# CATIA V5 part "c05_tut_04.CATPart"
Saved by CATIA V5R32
Part number: Part1
Bounding box of the stored display mesh (mm): x -150 to 0, y -16 to 54, z 0 to 74.999
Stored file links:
  D:\PROJECTS\Project 2022\CATIA V5 6R 2022\Resources\Tutorial Files\c05_catia_v5_6r2022_tut\c05_tut_04.CATPart
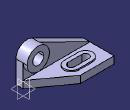
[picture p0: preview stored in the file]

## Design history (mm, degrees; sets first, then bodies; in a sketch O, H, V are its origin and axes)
Body1 (main body)
  Sketch1 on xy-plane, origin (0, 0, 0), H (1, 0, 0), V (0, 1, 0)
    line L1 (0, 0) -> (-150, 0)
    line L2 (-150, 0) -> (-150, 54)
    line L3 (-150, 54) -> (-75, 54)
    line L4 (-75, 54) -> (0, 0)
    length L2 = 54
    length L3 = 75
    length L1 = 150
    vertical: L2 V
    horizontal: L3 H, L1 H
  Pad1: profile Sketch1, direction (0, 0, 1), length 16
  Sketch2 on end face of Pad1, origin (0, 0, 16), H (1, 0, 0), V (0, 1, 0)
    construction line L1 (-114, 26) -> (-82, 26)
    point P1 (-114, 26)
    line L2 (-114, 42) -> (-82, 42)
    line L3 (-82, 10) -> (-114, 10)
    arc A1 centre (-82, 26) radius 16 from (-82, 42) to (-82, 10) cw
    arc A2 centre (-114, 26) radius 16 from (-114, 10) to (-114, 42) cw
    reference projected line E1 (-150, 0) -> (0, 0) from edge [face of Pad1 from Sketch1.L1 | end face of Pad1]
    reference projected line E2 (-150, 54) -> (-150, 0) from edge [face of Pad1 from Sketch1.L2 | end face of Pad1]
    distance L1 L2 = 16
    distance L3 E1 = 10
    length L2 = 32
    distance P1 E2 = 36
    horizontal: L1 H
    tangency: A1 L2, A2 L2, A1 L3, A2 L3
  Pad2: profile Sketch2, direction (0, 0, 1), length 3
  Sketch3 on face of Pad1 from Sketch1.L1, origin (0, 0, 0), H (1, 0, 0), V (0, 0, 1)
    line L1 (0, 0) -> (0, 50)
    arc A1 centre (-25, 50) radius 25 from (0, 50) to (-36.0939, 72.4037) ccw
    line L2 (-36.0939, 72.4037) -> (-150, 16)
    point P4 (-150, 16)
    line L3 (-150, 16) -> (-150, 0)
    point P5 (-150, 0)
    line L4 (-150, 0) -> (0, 0)
    reference projected line E1 (-150, 0) -> (-150, 16) from edge [face of Pad1 from Sketch1.L1 | face of Pad1 from Sketch1.L2]
    reference projected line E2 (-150, 16) -> (0, 16) from edge [face of Pad1 from Sketch1.L1 | end face of Pad1]
    radius A1 = 25
    length L1 = 50
    vertical: L1 V, L3 V
    tangency: A1 L1, L2 A1
    coincidence: P5 H, L3 E1, P4 E2
    horizontal: L4 H
  Pad3: profile Sketch3, direction (0, -1, 0), length 16
  Sketch4 on start face of Pad3, origin (0, 0, 0), H (-1, 0, 0), V (0, 0, 1)
    circle A1 centre (25, 50) radius 25
    reference projected arc E1 centre (25, 50) radius 25 from (37.6005, 71.5923) to (0, 50) ccw from edge [start face of Pad3 | face of Pad3 from Sketch3.A1]
    radius A1 = 25
    concentricity: A1 E1
  Pad4: profile Sketch4, direction (0, 1, 0), length 9
  Sketch5 on end face of Pad4, origin (0, 9, 0), H (-1, 0, 0), V (0, 0, 1)
    circle A1 centre (25, 50) radius 12.5
    reference projected circle E1 centre (25, 50) radius 25 from edge [face of Pad4 from Sketch4.A1 | end face of Pad4]
    radius A1 = 12.5
    concentricity: A1 E1
  Pocket1: profile Sketch5, direction (0, -1, 0), through (limit type 3)
  Sketch6 on end face of Pad2, origin (0, 0, 19), H (1, 0, 0), V (0, 1, 0)
    construction line L1 (-114, 26) -> (-82, 26)
    line L2 (-114, 34) -> (-82, 34)
    line L3 (-82, 18) -> (-114, 18)
    arc A1 centre (-82, 26) radius 8 from (-82, 34) to (-82, 18) cw
    arc A2 centre (-114, 26) radius 8 from (-114, 18) to (-114, 34) cw
    reference projected arc E1 centre (-114, 26) radius 16 from (-114, 42) to (-114, 10) ccw from edge [face of Pad2 from Sketch2.A2 | end face of Pad2]
    reference projected arc E2 centre (-82, 26) radius 16 from (-82, 10) to (-82, 42) ccw from edge [face of Pad2 from Sketch2.A1 | end face of Pad2]
    distance L2 L1 = 8
    horizontal: L1 H
    tangency: A1 L2, A2 L2, A1 L3, A2 L3
    concentricity: A2 E1, A1 E2
  Pocket2: profile Sketch6, direction (0, 0, -1), through (limit type 3)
